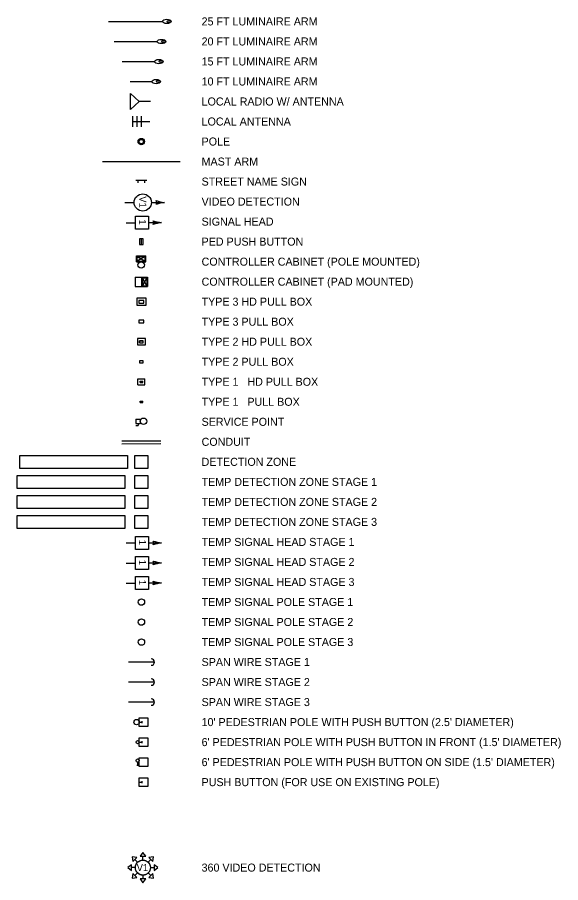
# Model space of a CAD drawing. Extents: x 998065 to 998820, y 1984965 to 1986752.
# Drawn here: x 998064.8 to 998317.3, y 1986349.6 to 1986751.6 of the extents above; entities that cross this region are included whole.
import ezdxf

# ---------------------------------------------------------------- set-up
doc = ezdxf.new("R2010")
doc.units = 0
for name, color, linetype in [('_CIVIL_CONSTRUCTION', 7, 'Continuous'), ('DSN_RDWY_Alignment Annotation', 7, 'Continuous'), ('DSN_ROW_Line-Annotation', 7, 'Continuous'), ('DSN_ROW_Point', 7, 'Continuous'), ('EX_ALIGNMENT', 7, 'Continuous'), ('EX_ROW', 7, 'Continuous'), ('S_CROSS_DRAIN', 7, 'Continuous'), ('S_CURB', 7, 'Continuous'), ('S_DRIVEWAY', 7, 'Continuous'), ('S_EDGE_PAVEMENT', 7, 'Continuous'), ('S_HWY_SYMBOLS', 7, 'Continuous'), ('S_HWY_TEXT', 7, 'Continuous'), ('S_ORTHO_IMAGE', 7, 'Continuous'), ('S_PARKING', 7, 'Continuous'), ('S_PAVEMENT_CROWN', 7, 'Continuous'), ('S_SHOULDER', 7, 'Continuous'), ('S_SIDE_DRAIN', 7, 'Continuous'), ('S_SIDEWALK', 7, 'Continuous'), ('S_WALL', 7, 'Continuous'), ('S_WALL_ANNOT', 7, 'Continuous')]:
    doc.layers.add(name, color=color, linetype=linetype)

msp = doc.modelspace()

# ---------------------------------------------------------------- linework, layer by layer
at = {"layer": '_CIVIL_CONSTRUCTION'}
for p, q in [((998064.78, 1986520.14), (998114.78, 1986520.16)), ((998064.79, 1986514.14), (998064.78, 1986520.14)), ((998114.78, 1986520.16), (998114.79, 1986514.16)), ((998114.79, 1986514.16), (998064.79, 1986514.14))]:
    msp.add_line(p, q, dxfattribs=at)
msp.add_lwpolyline([(998125.46, 1986514.17), (998119.46, 1986514.16), (998119.46, 1986520.16), (998125.46, 1986520.17)], close=True, dxfattribs=at)
at = {"layer": 'DSN_RDWY_Alignment Annotation'}
for p, q in [((998115.35, 1986498.09), (998119.69, 1986498.09)), ((998125.76, 1986498.12), (998131.8, 1986498.12))]:
    msp.add_line(p, q, dxfattribs=at)
msp.add_lwpolyline([(998119.69, 1986495.08), (998119.69, 1986501.14), (998125.76, 1986501.14), (998125.76, 1986495.08)], close=True, dxfattribs=at)
for centre, radius, start, end in [((998126.53, 1986498.12), 1.63, 328.1778, 31.8725), ((998136.2, 1986527.26), 29.47, 253.6787, 261.4168), ((998136.22, 1986468.98), 29.47, 98.6335, 106.3716)]:
    msp.add_arc(centre, radius, start, end, dxfattribs=at)
at = {"layer": 'DSN_ROW_Line-Annotation'}
for p, q in [((998115.35, 1986507.39), (998119.69, 1986507.39)), ((998125.76, 1986507.42), (998131.8, 1986507.42))]:
    msp.add_line(p, q, dxfattribs=at)
msp.add_lwpolyline([(998119.69, 1986504.38), (998119.69, 1986510.44), (998125.76, 1986510.44), (998125.76, 1986504.38)], close=True, dxfattribs=at)
for centre, radius, start, end in [((998126.53, 1986507.42), 1.63, 328.1778, 31.8725), ((998136.2, 1986536.56), 29.47, 253.6787, 261.4168), ((998136.22, 1986478.28), 29.47, 98.6335, 106.3716)]:
    msp.add_arc(centre, radius, start, end, dxfattribs=at)
at = {"layer": 'DSN_ROW_Point'}
for p, q in [((998115.35, 1986488.79), (998119.69, 1986488.79)), ((998125.76, 1986488.82), (998131.8, 1986488.82))]:
    msp.add_line(p, q, dxfattribs=at)
msp.add_lwpolyline([(998119.69, 1986485.78), (998119.69, 1986491.84), (998125.76, 1986491.84), (998125.76, 1986485.78)], close=True, dxfattribs=at)
for centre, radius, start, end in [((998126.53, 1986488.82), 1.63, 328.1778, 31.8725), ((998136.2, 1986517.96), 29.47, 253.6787, 261.4168), ((998136.22, 1986459.68), 29.47, 98.6335, 106.3716)]:
    msp.add_arc(centre, radius, start, end, dxfattribs=at)
at = {"layer": 'EX_ALIGNMENT'}
msp.add_line((998128.46, 1986433.47), (998116.46, 1986433.46), dxfattribs=at)
msp.add_circle((998122.45, 1986461.36), 1.5, dxfattribs=at)
msp.add_arc((998126.96, 1986433.47), 1.5, 270.0252, 90.0252, dxfattribs=at)
at = {"layer": 'EX_ROW'}
msp.add_line((998128.46, 1986442.77), (998116.46, 1986442.76), dxfattribs=at)
msp.add_circle((998122.45, 1986470.66), 1.5, dxfattribs=at)
msp.add_arc((998126.96, 1986442.77), 1.5, 270.0252, 90.0252, dxfattribs=at)
at = {"layer": 'S_CROSS_DRAIN'}
msp.add_lwpolyline([(998121.55, 1986648.68), (998121.55, 1986646.05), (998122.43, 1986646.05), (998122.43, 1986648.68)], close=True, dxfattribs=at)
at = {"layer": 'S_CURB'}
for p, q in [((998119.56, 1986630.93), (998125.3, 1986630.93)), ((998119.56, 1986630.93), (998119.56, 1986626.6)), ((998122.56, 1986630.93), (998122.56, 1986626.6)), ((998122.89, 1986630.6), (998122.89, 1986626.93)), ((998124.97, 1986626.93), (998122.89, 1986630.6)), ((998122.89, 1986630.6), (998124.97, 1986630.6)), ((998124.97, 1986630.58), (998122.89, 1986626.93)), ((998124.97, 1986630.6), (998124.97, 1986626.93)), ((998125.3, 1986630.93), (998125.3, 1986626.6)), ((998119.56, 1986626.6), (998125.3, 1986626.6)), ((998122.89, 1986626.93), (998124.97, 1986626.93))]:
    msp.add_line(p, q, dxfattribs=at)
at = {"layer": 'S_DRIVEWAY'}
for p, q in [((998119.94, 1986564.92), (998119.94, 1986562.92)), ((998119.94, 1986564.92), (998121.94, 1986564.92)), ((998121.94, 1986564.92), (998121.94, 1986562.92)), ((998119.94, 1986562.92), (998121.94, 1986562.92)), ((998119.94, 1986561.92), (998120.94, 1986561.92)), ((998120.94, 1986562.92), (998120.94, 1986561.92)), ((998113.38, 1986554.86), (998131.51, 1986554.87)), ((998113.38, 1986553.53), (998131.51, 1986553.54))]:
    msp.add_line(p, q, dxfattribs=at)
msp.add_circle((998123.44, 1986563.92), 1.5, dxfattribs=at)
at = {"layer": 'S_EDGE_PAVEMENT'}
msp.add_line((998104.4, 1986684.56), (998140.4, 1986684.58), dxfattribs=at)
for centre, radius in [((998122.4, 1986693.87), 1.5), ((998122.4, 1986693.87), 1.25), ((998122.4, 1986693.87), 1), ((998122.45, 1986479.96), 1.5), ((998120.21, 1986424.17), 1.25), ((998120.71, 1986414.86), 0.75), ((998120.71, 1986406.31), 0.75)]:
    msp.add_circle(centre, radius, dxfattribs=at)
at = {"layer": 'S_HWY_SYMBOLS'}
for p, q in [((998064.78, 1986529.44), (998114.78, 1986529.46)), ((998064.79, 1986523.44), (998064.78, 1986529.44)), ((998114.78, 1986529.46), (998114.79, 1986523.46)), ((998114.79, 1986523.46), (998064.79, 1986523.44))]:
    msp.add_line(p, q, dxfattribs=at)
msp.add_lwpolyline([(998125.46, 1986523.47), (998119.46, 1986523.46), (998119.46, 1986529.46), (998125.46, 1986529.47)], close=True, dxfattribs=at)
at = {"layer": 'S_HWY_TEXT'}
for p, q in [((998064.78, 1986538.74), (998114.78, 1986538.76)), ((998064.79, 1986532.74), (998064.78, 1986538.74)), ((998114.78, 1986538.76), (998114.79, 1986532.76)), ((998114.79, 1986532.76), (998064.79, 1986532.74))]:
    msp.add_line(p, q, dxfattribs=at)
msp.add_lwpolyline([(998125.46, 1986532.77), (998119.46, 1986532.76), (998119.46, 1986538.76), (998125.46, 1986538.77)], close=True, dxfattribs=at)
at = {"layer": 'S_ORTHO_IMAGE'}
msp.add_line((998128.46, 1986452.07), (998116.46, 1986452.06), dxfattribs=at)
msp.add_arc((998126.96, 1986452.07), 1.5, 270.0252, 90.0252, dxfattribs=at)
at = {"layer": 'S_PARKING'}
for p, q in [((998065.94, 1986548.04), (998115.94, 1986548.06)), ((998065.94, 1986542.04), (998065.94, 1986548.04)), ((998115.94, 1986548.06), (998115.94, 1986542.06)), ((998115.94, 1986542.06), (998065.94, 1986542.04))]:
    msp.add_line(p, q, dxfattribs=at)
msp.add_lwpolyline([(998125.46, 1986542.07), (998119.46, 1986542.06), (998119.46, 1986548.06), (998125.46, 1986548.07)], close=True, dxfattribs=at)
at = {"layer": 'S_PAVEMENT_CROWN'}
for p, q in [((998114.75, 1986665.57), (998119.08, 1986665.57)), ((998127.08, 1986665.58), (998133.15, 1986665.58)), ((998115.35, 1986656.19), (998119.69, 1986656.19)), ((998125.76, 1986656.22), (998131.8, 1986656.22)), ((998123.14, 1986363.59), (998121.83, 1986361.83)), ((998124.45, 1986361.83), (998123.14, 1986363.59)), ((998120.35, 1986361.22), (998118.18, 1986361.54)), ((998118.18, 1986361.54), (998118.5, 1986359.37)), ((998118.5, 1986359.37), (998120.35, 1986361.22)), ((998120.66, 1986359.06), (998119.43, 1986360.3)), ((998121.83, 1986361.83), (998124.45, 1986361.83)), ((998123.14, 1986360.08), (998123.14, 1986361.83)), ((998125.61, 1986359.06), (998126.85, 1986360.3)), ((998128.09, 1986361.54), (998125.92, 1986361.22)), ((998125.92, 1986361.22), (998127.78, 1986359.37)), ((998127.78, 1986359.37), (998128.09, 1986361.54)), ((998117.89, 1986357.89), (998116.13, 1986356.58)), ((998116.13, 1986356.58), (998117.89, 1986355.27)), ((998117.89, 1986355.27), (998117.89, 1986357.89)), ((998119.64, 1986356.58), (998117.89, 1986356.58)), ((998126.64, 1986356.58), (998128.39, 1986356.58)), ((998128.39, 1986357.9), (998128.39, 1986355.27)), ((998130.15, 1986356.59), (998128.39, 1986357.9)), ((998128.39, 1986355.27), (998130.15, 1986356.59)), ((998118.5, 1986353.8), (998118.18, 1986351.63)), ((998118.18, 1986351.63), (998120.36, 1986351.94)), ((998120.36, 1986351.94), (998118.5, 1986353.8)), ((998120.66, 1986354.11), (998119.43, 1986352.87)), ((998123.14, 1986353.08), (998123.14, 1986351.33)), ((998125.62, 1986354.11), (998126.85, 1986352.87)), ((998127.78, 1986353.8), (998125.93, 1986351.94)), ((998125.93, 1986351.94), (998128.1, 1986351.63)), ((998128.1, 1986351.63), (998127.78, 1986353.8)), ((998124.45, 1986351.33), (998121.83, 1986351.33)), ((998121.83, 1986351.33), (998123.14, 1986349.57)), ((998123.14, 1986349.57), (998124.45, 1986351.33))]:
    msp.add_line(p, q, dxfattribs=at)
for points in [[(998119.69, 1986653.18), (998119.69, 1986659.24), (998125.76, 1986659.24), (998125.76, 1986653.18)], [(998120.46, 1986358.83), (998120.66, 1986359.06), (998120.89, 1986359.26), (998121.13, 1986359.45), (998121.39, 1986359.61), (998121.66, 1986359.75), (998121.94, 1986359.87), (998122.23, 1986359.96), (998122.53, 1986360.03), (998122.83, 1986360.07), (998123.14, 1986360.08), (998123.44, 1986360.07), (998123.74, 1986360.03), (998124.04, 1986359.96), (998124.33, 1986359.87), (998124.61, 1986359.76), (998124.89, 1986359.61), (998125.14, 1986359.45), (998125.39, 1986359.27), (998125.61, 1986359.06), (998125.82, 1986358.83), (998126.01, 1986358.59), (998126.17, 1986358.33), (998126.31, 1986358.06), (998126.43, 1986357.78), (998126.52, 1986357.49), (998126.59, 1986357.19), (998126.63, 1986356.89), (998126.64, 1986356.58), (998126.63, 1986356.28), (998126.59, 1986355.98), (998126.52, 1986355.68), (998126.43, 1986355.39), (998126.31, 1986355.1), (998126.17, 1986354.83), (998126.01, 1986354.58), (998125.82, 1986354.33), (998125.62, 1986354.11), (998125.39, 1986353.9), (998125.39, 1986353.9), (998125.15, 1986353.72), (998124.89, 1986353.55), (998124.62, 1986353.41), (998124.34, 1986353.29), (998124.05, 1986353.2), (998123.75, 1986353.14), (998123.45, 1986353.1), (998123.14, 1986353.08), (998122.84, 1986353.1), (998122.53, 1986353.14), (998122.24, 1986353.2), (998121.95, 1986353.29), (998121.66, 1986353.41), (998121.39, 1986353.55), (998121.13, 1986353.71), (998120.89, 1986353.9), (998120.67, 1986354.11), (998120.46, 1986354.33), (998120.27, 1986354.57), (998120.11, 1986354.83), (998119.97, 1986355.1), (998119.85, 1986355.38), (998119.76, 1986355.68), (998119.69, 1986355.97), (998119.65, 1986356.28), (998119.64, 1986356.58), (998119.65, 1986356.89), (998119.69, 1986357.19), (998119.76, 1986357.49), (998119.85, 1986357.78), (998119.97, 1986358.06), (998120.11, 1986358.33), (998120.27, 1986358.59)]]:
    msp.add_lwpolyline(points, close=True, dxfattribs=at)
for centre, radius in [((998123.08, 1986665.58), 4), ((998123.14, 1986356.58), 3.5)]:
    msp.add_circle(centre, radius, dxfattribs=at)
for centre, radius, start, end in [((998127.88, 1986665.58), 1.63, 328.1778, 31.8725), ((998137.55, 1986694.72), 29.47, 253.6787, 261.4168), ((998137.57, 1986636.44), 29.47, 98.6335, 106.3716), ((998126.53, 1986656.22), 1.63, 328.1778, 31.8725), ((998136.2, 1986685.36), 29.47, 253.6787, 261.4168), ((998136.22, 1986627.08), 29.47, 98.6335, 106.3716)]:
    msp.add_arc(centre, radius, start, end, dxfattribs=at)
at = {"layer": 'S_SHOULDER'}
for points in [[(998121.46, 1986426.16), (998125.46, 1986426.17), (998125.46, 1986422.17), (998121.46, 1986422.16)], [(998121.46, 1986416.86), (998125.46, 1986416.87), (998125.46, 1986412.87), (998121.46, 1986412.86)], [(998121.46, 1986407.56), (998125.46, 1986407.57), (998125.46, 1986403.57), (998121.46, 1986403.56)], [(998121.46, 1986398.26), (998125.46, 1986398.27), (998125.46, 1986394.27), (998121.46, 1986394.26)]]:
    msp.add_lwpolyline(points, close=True, dxfattribs=at)
at = {"layer": 'S_SIDE_DRAIN'}
for p, q in [((998124.91, 1986675.76), (998119.91, 1986675.76)), ((998120.91, 1986674.76), (998120.91, 1986675.76)), ((998123.91, 1986675.76), (998123.91, 1986674.76)), ((998124.91, 1986675.76), (998123.91, 1986675.76))]:
    msp.add_line(p, q, dxfattribs=at)
at = {"layer": 'S_SIDEWALK'}
for p, q in [((998124.6, 1986621.1), (998120.27, 1986621.09)), ((998120.27, 1986621.09), (998120.27, 1986617.82)), ((998124.6, 1986617.83), (998124.6, 1986621.1)), ((998120.27, 1986617.82), (998124.6, 1986617.83)), ((998121.27, 1986620.1), (998121.27, 1986618.82)), ((998123.6, 1986620.1), (998121.27, 1986620.1)), ((998121.27, 1986618.82), (998123.6, 1986618.83)), ((998123.6, 1986618.83), (998123.6, 1986620.1)), ((998121.26, 1986610.97), (998121.26, 1986609.7)), ((998123.6, 1986610.97), (998121.26, 1986610.97)), ((998121.26, 1986609.7), (998123.6, 1986609.7)), ((998123.6, 1986609.7), (998123.6, 1986610.97)), ((998124.31, 1986602.32), (998120.56, 1986602.32)), ((998120.56, 1986602.32), (998120.56, 1986599.4)), ((998121.56, 1986600.4), (998121.56, 1986601.32)), ((998121.56, 1986601.32), (998123.31, 1986601.32)), ((998121.56, 1986601.32), (998121.56, 1986600.4)), ((998123.31, 1986601.32), (998121.56, 1986601.32)), ((998123.31, 1986600.4), (998123.31, 1986601.32)), ((998123.31, 1986600.4), (998123.31, 1986601.32)), ((998124.31, 1986599.4), (998124.31, 1986602.32)), ((998120.56, 1986599.4), (998124.31, 1986599.4)), ((998121.56, 1986600.4), (998123.31, 1986600.4)), ((998121.56, 1986600.4), (998123.31, 1986600.4)), ((998121.56, 1986592.02), (998121.56, 1986591.1)), ((998123.31, 1986592.02), (998121.56, 1986592.02)), ((998121.56, 1986591.1), (998123.31, 1986591.1)), ((998123.31, 1986591.1), (998123.31, 1986592.02)), ((998121.46, 1986424.16), (998122.78, 1986424.16)), ((998122.78, 1986423.73), (998122.78, 1986424.6)), ((998121.46, 1986414.86), (998122.78, 1986414.86)), ((998122.78, 1986414.43), (998122.78, 1986415.3)), ((998120.27, 1986404.25), (998121.15, 1986404.24)), ((998120.71, 1986405.56), (998120.71, 1986404.25)), ((998121.46, 1986396.26), (998122.78, 1986396.26)), ((998122.78, 1986395.83), (998122.78, 1986396.7))]:
    msp.add_line(p, q, dxfattribs=at)
msp.add_lwpolyline([(998121.55, 1986646.05), (998123.3, 1986646.04), (998123.3, 1986648.68), (998121.55, 1986648.68)], close=True, dxfattribs=at)
at = {"layer": 'S_WALL'}
for p, q in [((998107.23, 1986749.65), (998132.23, 1986749.66)), ((998109.83, 1986740.35), (998129.83, 1986740.36)), ((998113.54, 1986731.06), (998128.54, 1986731.06)), ((998117.26, 1986721.76), (998127.26, 1986721.76)), ((998117.39, 1986708.74), (998117.38, 1986716.24)), ((998117.38, 1986716.24), (998121.39, 1986712.49)), ((998121.39, 1986712.49), (998117.39, 1986708.74)), ((998126.74, 1986712.5), (998121.39, 1986712.49)), ((998118.32, 1986705.65), (998118.32, 1986700.65)), ((998120.32, 1986705.65), (998120.32, 1986700.65)), ((998122.32, 1986705.66), (998122.32, 1986700.66)), ((998118.32, 1986703.15), (998126.32, 1986703.16)), ((998120.18, 1986638.04), (998120.18, 1986640.78)), ((998120.18, 1986640.78), (998124.51, 1986640.78)), ((998120.18, 1986638.04), (998124.51, 1986638.04)), ((998120.51, 1986640.45), (998124.18, 1986640.45)), ((998120.51, 1986638.37), (998120.51, 1986640.45)), ((998124.18, 1986640.45), (998120.51, 1986638.37)), ((998120.51, 1986638.37), (998124.18, 1986638.37)), ((998120.53, 1986640.45), (998124.18, 1986638.37)), ((998124.18, 1986638.37), (998124.18, 1986640.45)), ((998124.51, 1986638.04), (998124.51, 1986640.78)), ((998120.85, 1986583.62), (998124.04, 1986583.63)), ((998120.85, 1986580.9), (998120.85, 1986583.62)), ((998120.85, 1986580.9), (998124.04, 1986580.9)), ((998121.85, 1986581.9), (998121.85, 1986582.63)), ((998121.85, 1986582.63), (998123.04, 1986582.63)), ((998121.85, 1986581.9), (998123.04, 1986581.9)), ((998123.04, 1986581.9), (998123.04, 1986582.63)), ((998124.04, 1986580.9), (998124.04, 1986583.63)), ((998121.85, 1986572.6), (998121.85, 1986573.33)), ((998121.85, 1986573.33), (998123.04, 1986573.33)), ((998123.04, 1986572.6), (998123.04, 1986573.33)), ((998121.85, 1986572.6), (998123.04, 1986572.6))]:
    msp.add_line(p, q, dxfattribs=at)
msp.add_circle((998122.35, 1986636.54), 1.5, dxfattribs=at)
for centre, major_axis in [((998134.23, 1986749.67), (2, 0)), ((998135.23, 1986749.67), (-1, 0)), ((998131.83, 1986740.36), (2, 0)), ((998132.83, 1986740.36), (-1, 0)), ((998130.54, 1986731.06), (2, 0)), ((998131.54, 1986731.06), (-1, 0)), ((998129.26, 1986721.76), (2, 0)), ((998130.26, 1986721.76), (-1, 0))]:
    msp.add_ellipse(centre, major_axis=major_axis, ratio=0.5, dxfattribs=at)

# ---------------------------------------------------------------- texts
at = {"layer": 'DSN_RDWY_Alignment Annotation'}
msp.add_text('1', height=3.25, rotation=270.0252, dxfattribs=at).set_placement((998121.34, 1986499.58))
at = {"layer": 'DSN_ROW_Line-Annotation'}
msp.add_text('1', height=3.25, rotation=270.0252, dxfattribs=at).set_placement((998121.34, 1986508.88))
at = {"layer": 'DSN_ROW_Point'}
msp.add_text('1', height=3.25, rotation=270.0252, dxfattribs=at).set_placement((998121.34, 1986490.28))
at = {"layer": 'S_PAVEMENT_CROWN'}
for s, rotation, p in [('V1', 270.0252, (998121.49, 1986668.46)), ('1', 270.0252, (998121.34, 1986657.68)), ('V1', 0.0252, (998120.26, 1986354.99))]:
    msp.add_text(s, height=3.25, rotation=rotation, dxfattribs=at).set_placement(p)
at = {"layer": 'S_WALL_ANNOT'}
for s, p in [('25 FT LUMINAIRE ARM', (998150.42, 1986747.83)), ('20 FT LUMINAIRE ARM', (998150.42, 1986738.53)), ('15 FT LUMINAIRE ARM', (998150.42, 1986729.23)), ('10 FT LUMINAIRE ARM', (998150.42, 1986719.93)), ('LOCAL RADIO W/ ANTENNA', (998150.42, 1986710.63)), ('LOCAL ANTENNA', (998150.42, 1986701.33)), ('POLE', (998150.42, 1986692.03)), ('MAST ARM', (998150.42, 1986682.73)), ('STREET NAME SIGN', (998150.42, 1986673.43)), ('VIDEO DETECTION', (998150.42, 1986664.13)), ('SIGNAL HEAD', (998150.42, 1986654.83)), ('PED PUSH BUTTON', (998150.42, 1986645.53)), ('CONTROLLER CABINET (POLE MOUNTED)', (998150.42, 1986636.23)), ('CONTROLLER CABINET (PAD MOUNTED)', (998150.42, 1986626.93)), ('TYPE 3 HD PULL BOX', (998150.42, 1986617.63)), ('TYPE 3 PULL BOX', (998150.42, 1986608.33)), ('TYPE 2 HD PULL BOX', (998150.42, 1986599.03)), ('TYPE 2 PULL BOX', (998150.42, 1986589.73)), ('TYPE 1   HD PULL BOX', (998150.42, 1986580.43)), ('TYPE 1   PULL BOX', (998150.42, 1986571.13)), ('SERVICE POINT', (998150.42, 1986561.83)), ('CONDUIT', (998150.42, 1986552.53)), ('DETECTION ZONE', (998150.42, 1986543.23)), ('TEMP DETECTION ZONE STAGE 1', (998150.42, 1986533.93)), ('TEMP DETECTION ZONE STAGE 2', (998150.42, 1986524.63)), ('TEMP DETECTION ZONE STAGE 3', (998150.42, 1986515.33)), ('TEMP SIGNAL HEAD STAGE 1', (998150.42, 1986506.03)), ('TEMP SIGNAL HEAD STAGE 2', (998150.42, 1986496.73)), ('TEMP SIGNAL HEAD STAGE 3', (998150.42, 1986487.43)), ('TEMP SIGNAL POLE STAGE 1', (998150.42, 1986478.13)), ('TEMP SIGNAL POLE STAGE 2', (998150.42, 1986468.83)), ('TEMP SIGNAL POLE STAGE 3', (998150.42, 1986459.53)), ('SPAN WIRE STAGE 1', (998150.42, 1986450.23)), ('SPAN WIRE STAGE 2', (998150.42, 1986440.93)), ('SPAN WIRE STAGE 3', (998150.42, 1986431.63)), ("10' PEDESTRIAN POLE WITH PUSH BUTTON (2.5' DIAMETER)", (998150.42, 1986422.33)), ("6' PEDESTRIAN POLE WITH PUSH BUTTON IN FRONT (1.5' DIAMETER)", (998150.42, 1986413.03)), ("6' PEDESTRIAN POLE WITH PUSH BUTTON ON SIDE (1.5' DIAMETER)", (998150.42, 1986403.73)), ('PUSH BUTTON (FOR USE ON EXISTING POLE)', (998150.42, 1986394.43)), ('360 VIDEO DETECTION', (998150.42, 1986354.73))]:
    msp.add_text(s, height=3.72, dxfattribs=at).set_placement(p)

doc.saveas('drawing.dxf')
